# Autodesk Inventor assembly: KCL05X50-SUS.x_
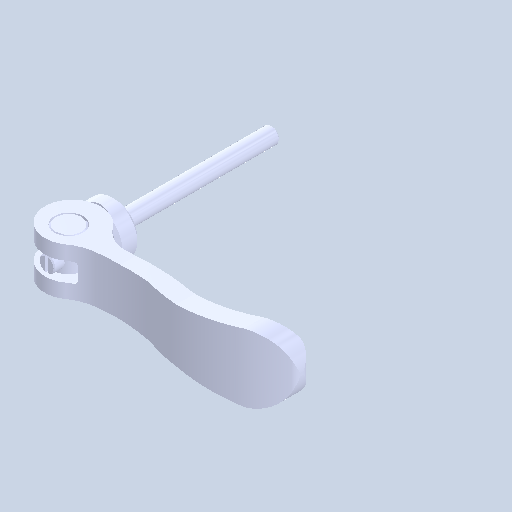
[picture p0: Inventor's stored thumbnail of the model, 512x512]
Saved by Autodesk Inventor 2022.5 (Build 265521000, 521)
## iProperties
Created: 2024-08
Part Number: KCL05X50-SUS.x_
Document SubType Name: Assembly
Designer: ImaoCorp
Author: ImaoCorp
Sending System: SOLIDWORKS 2022-2022290
MC: AMD64
MC_MODEL: Intel64 Family 6 Model 60 Stepping 3, GenuineIntel
OS: Windows_NT
FRU: Parasolid Version 33.1, build 260,  4-25-2022
FORMAT: text
GUISE: transmit
KEY: FILEKCL05X50-SUS.x_t
DATE: Thu Aug 29 10:49:25 2024
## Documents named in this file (5)
- Y:\5.更新分\2024年対応\1001_KCL\データ\kcl05x50-sus\KCL05X50-SUS.x_.iam
- Y:\5.更新分\2024年対応\1001_KCL\データ\kcl05x50-sus\KCL05X50-SUS_01.ipt
- Y:\5.更新分\2024年対応\1001_KCL\データ\kcl05x50-sus\KCL05X50-SUS_02.ipt
- Y:\5.更新分\2024年対応\1001_KCL\データ\kcl05x50-sus\KCL05X50-SUS_03.ipt
- Y:\5.更新分\2024年対応\1001_KCL\データ\kcl05x50-sus\KCL05X50-SUS_04.ipt
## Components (4 placed, 4 different names)
1. KCL05X50-SUS_01
2. KCL05X50-SUS_02
3. KCL05X50-SUS_03
4. KCL05X50-SUS_04
